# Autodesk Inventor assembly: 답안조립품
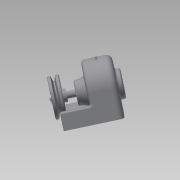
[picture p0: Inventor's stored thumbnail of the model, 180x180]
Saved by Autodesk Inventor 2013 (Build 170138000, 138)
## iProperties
Created: 2015-02
Part Number: 답안조립품
Document SubType Name: Assembly
Designer: Administrator
Author: Administrator
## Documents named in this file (14)
- C:\Users\Administrator\Desktop\450216V1014\답안조립품.iam
- C:\Users\Administrator\Desktop\450216V1014\본체.ipt
- C:\Users\Administrator\Desktop\450216V1014\베어링 6001.ipt
- C:\Users\Administrator\Desktop\450216V1014\축.ipt
- C:\Users\Administrator\Desktop\450216V1014\키5x5.ipt
- C:\Users\Administrator\Desktop\450216V1014\스퍼기어.ipt
- C:\Users\Administrator\Desktop\450216V1014\축커버.ipt
- C:\Users\Administrator\Desktop\450216V1014\오일실.ipt
- C:\Users\Administrator\Desktop\450216V1014\키4x4.ipt
- C:\Users\Administrator\Desktop\450216V1014\벨트폴리.ipt
- C:\Users\Administrator\Desktop\450216V1014\와샤.ipt
- C:\Users\Administrator\Desktop\450216V1014\M5x0.8.ipt
- M5x0.8.ipt
- C:\Users\Administrator\Desktop\450216V1014\M3x0.5.ipt
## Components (5 placed, 2 different names)
1. M5x0.8:1
2. M3x0.5:1
3. M3x0.5:2
4. M3x0.5:3
5. M3x0.5:4
